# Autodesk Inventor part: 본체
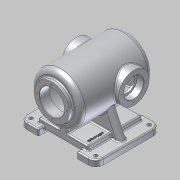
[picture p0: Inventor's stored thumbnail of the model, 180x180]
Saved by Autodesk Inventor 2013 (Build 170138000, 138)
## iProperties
Created: 2013-06
Part Number: 본체
Document SubType Name: Modeling
Designer: SeoGD™[esajin.kr]
Density: 1 g/cm^3
Material: 일반
Author: SeoGD™[esajin.kr]
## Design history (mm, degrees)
sketch "스케치1"
  geometry: L1 (-100, 85)-(-50, 85); L2 (-50, 85)-(-50, -85); L3 (-50, -85)-(-100, -85); L4 (-100, -85)-(-100, 85); L5 (50, 85)-(100, 85); L6 (100, 85)-(100, -85); L7 (100, -85)-(50, -85); L8 (50, -85)-(50, 85); 3 further points
  constraints: 16 end point, 4 parallel, 2 equal length, 2 horizontal, 2 horizontal alignment, 2 midpoint, 2 perpendicular
  dimensions: "d0" = 100 distance between parallel lines of L8 L2; "d1" = 170 distance of L3.end L1.start; "d3" = 200 distance between parallel lines of L6 L4; "d4" = 50 distance from line of point (0, 0) L2 (= 0.5 x d0)
extrude "돌출1" new body sketch "스케치1" distance "d5" = 16; taper "d6" = 0 deg
node "작업 평면1"
sketch "스케치2"
  geometry: L1 (-65, 70)-(65, 70); L2 (65, 70)-(65, -70); L3 (65, -70)-(-65, -70); L4 (-65, -70)-(-65, 70); 3 further points
  constraints: 8 end point, 2 midpoint, 2 parallel, 1 horizontal, 1 horizontal alignment, 1 perpendicular, 1 vertical alignment
  dimensions: "d8" = 130 distance of L2.end L3.end; "d9" = 140 distance of L1.end L2.end
extrude "돌출2" join sketch "스케치2" distance "d10" = 20; taper "d11" = 0 deg
sketch "스케치3"
  geometry: L1 (-100, 110)-(100, 110); L2 (85, 0)-(-85, 0) reference; L3 (100, 110)-(100, 175); L4 (100, 175)-(-90, 175); L5 (-90, 175)-(-90, 156); L6 (-90, 156)-(-100, 156); L7 (-100, 156)-(-100, 110); L8 (90, 110)-(90, 165); L9 (90, 165)-(-75, 165); L10 (-75, 165)-(-75, 110); L11 (-100, 142.5)-(-75, 142.5); 3 further points
  constraints: 20 end point, 5 perpendicular, 4 parallel, 4 point on line, 2 midpoint, 1 horizontal, 1 vertical alignment
  dimensions: "d12" = 110 distance from line of L2 L1.end; "d13" = 200 distance of L1.start L1.end; "d14" = 130 diameter of L4 L1; "d15" = 92 diameter of L6 L1; "d16" = 10 distance of L5.end L6.end; "d42" = 110 diameter of L9 L1; "d43" = 10 distance between parallel lines of L3 L8; "d44" = 25 distance between parallel lines of L10 L7; "d45" = 65 diameter of L11 L1
revolve "회전1" sketch "스케치3" stored, may be unused: angle "d17" = 90 deg
sketch "스케치4"
  geometry: L1 (-50, 70)-(50, 70) reference; L2 (50, -70)-(-50, -70) reference; L3 (-10, 70)-(-10, -70); L4 (10, -70)-(10, 70); 1 further point
  constraints: 4 end point, 4 point on line, 2 perpendicular
  dimensions: "d18" = 20 distance between parallel lines of L4 L3; "d19" = 10 distance from line of point (0, 0) L3
extrude "돌출3" join sketch "스케치4" stored distance "d20" = 10; taper "d21" = 0 deg
node "작업 평면2"
sketch "스케치5"
  geometry: L1 (-50, -8)-(0, -8) reference; L2 (100, -8)-(150, -8) reference; L3 (-40, -8)-(-8.943, -74.601); L4 (140, -8)-(108.943, -74.601); L5 (-50, 8)-(-50, -8) reference; L6 (150, 8)-(150, -8) reference; A1 r 65 centre (50, -102) between (-8.943, -74.601) and (108.943, -74.601) reference; 1 further point
  constraints: 4 end point, 2 point on circle, 2 point on line, 1 equal length
  dimensions: "d23" = 10 distance from line of L3.start L5; "d24" = 10 distance from line of L4.start L6; "d25" = 25 deg angle of L3 L5
feature "리브1" sketch "스케치5" dims "d26" = 1, "d27" = 20, "d28" = 0
node "작업 평면3"
sketch "스케치6"
  geometry: L1 (100, 156)-(100, 64) reference; C1 r 40 at (-40, 110); 2 further points
  constraints: 1 centre point, 1 horizontal alignment, 1 midpoint
  dimensions: "d37" = 80 diameter of C1; "d38" = 140 distance from line of C1.centre L1
extrude "돌출4" join sketch "스케치6" stored distance "d39" = 10; taper "d40" = 0 deg
hole "구멍1" diameter "d48" = 42; stored, may be unused: countersink angle "d52" = 90 deg, drill point angle "d54" = 118 deg; dims "d46" = 10, "d47" = 10, "d49" = 6, "d50" = 52, "d51" = 18, "d53" = 8
sketch "스케치7"
  geometry: C1 r 40 at (0, 0) reference; 2 further points
  constraints: 1 horizontal alignment
  dimensions: "d55" = 32.5 distance of point (32.5, 0) C1.centre
hole "구멍2" sketch "스케치7" at (32.5, 0) diameter "d56" = 3.242; stored, may be unused: countersink angle "d60" = 90 deg, drill point angle "d62" = 118 deg; dims "d57" = 10, "d58" = 52, "d59" = 18, "d61" = 13
sketch "스케치8"
  geometry: C1 r 46 at (0, 0) reference; 2 further points
  constraints: 1 vertical alignment
  dimensions: "d66" = 39 distance of C1.centre point (0, 39)
hole "구멍3" sketch "스케치8" at (0, 39) diameter "d67" = 3.242; stored, may be unused: countersink angle "d71" = 90 deg, drill point angle "d73" = 118 deg; dims "d68" = 10, "d69" = 52, "d70" = 18, "d72" = 13
fillet "모깎기7" dims "d77" = 20, "d78" = 13, "d79" = 3, "d80" = 10
fillet "모깎기8" dims "d81" = 3
fillet "모깎기9" dims "d82" = 3
fillet "모깎기10" dims "d83" = 3, "d84" = 0.3
chamfer "모따기1" distance "d85" = 1; stored, may be unused: second distance "d86" = 2, angle "d87" = 45 deg
node "작업 평면4"
sketch "스케치10"
  geometry: 5 further points
  constraints: 2 horizontal alignment, 2 vertical alignment
  dimensions: "d90" = 170 distance of point (85, 70) point (-85, 70); "d91" = 140 distance of point (-85, 70) point (-85, -70); "d92" = 70 vertical distance of point (0, 0) point (-85, -70) (= 0.5 x d91); "d93" = 85 horizontal distance of point (0, 0) point (-85, 70) (= 0.5 x d90)
hole "구멍4" sketch "스케치10" at (-85, 70), (85, 70), (85, -70), (-85, -70) diameter "d94" = 10; stored, may be unused: countersink angle "d98" = 90 deg, drill point angle "d100" = 118 deg; dims "d95" = 6, "d96" = 4, "d97" = 2, "d99" = 8
sketch "스케치11"
  geometry: L1 (13, -70)-(62, -70) reference; L2 (65, -67)-(65, -13) reference; 2 further points
  constraints: 1 other
  dimensions: "d101" = 30 distance from line of point (55, -40) L1; "d102" = 10 distance from line of point (55, -40) L2
feature "엠보싱2" sketch "스케치11" dims "d0" = 100, "d1" = 170, "d3" = 200, "d4" = 50 (= 0.5 x d0), "d103" = 1, "d104" = 0
node "솔리드1"
mirror "대칭1"
pattern_circular "원형 패턴1" dims angle "d64" = 360 deg
mirror "대칭3"
pattern_circular "원형 패턴2" dims angle "d75" = 360 deg
other parameters: "d7" = 8, "d36" = -75
